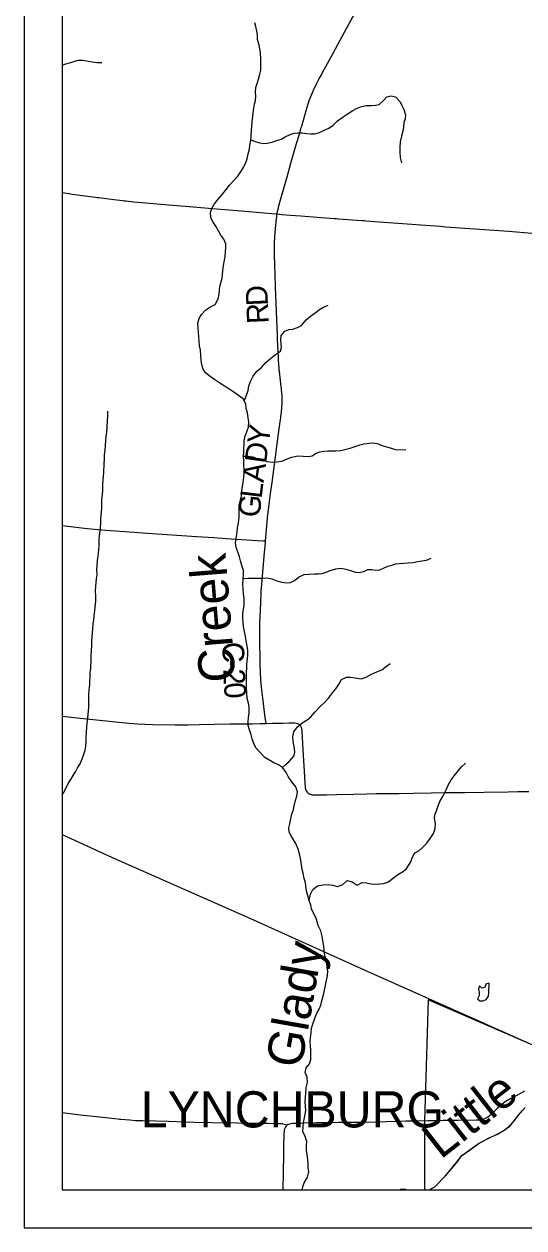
# Model space of a CAD drawing. Extents: x 0 to 48.6, y 0 to 22.
# Drawn here: x 2 to 3.311, y 14 to 17.154 of the extents above; entities that cross this region are included whole.
import ezdxf

# ---------------------------------------------------------------- set-up
doc = ezdxf.new("R2010")
doc.units = 0
for name, color, linetype in [('GM_X_Corporation', 7, 'Continuous'), ('GM_X_Corporation_Text', 7, 'Continuous'), ('GM_X_County_Road', 7, 'Continuous'), ('GM_X_County_Road_Text', 7, 'Continuous'), ('GM_X_Major_River', 7, 'Continuous'), ('GM_X_Major_River_Text', 7, 'Continuous'), ('GM_X_Minor_Lake', 7, 'Continuous'), ('GM_X_Minor_River', 7, 'Continuous'), ('GM_X_Minor_River_Text', 7, 'Continuous'), ('GM_X_Rail_Line', 7, 'Continuous'), ('GM_X_Township_Road', 7, 'Continuous'), ('SH_Data', 7, 'Continuous')]:
    doc.layers.add(name, color=color, linetype=linetype)

msp = doc.modelspace()

# ---------------------------------------------------------------- linework, layer by layer
at = {"layer": 'GM_X_Corporation'}
for points in [[(2.1, 20.9), (2.1, 14.1), (2.9857, 14.1), (2.9884, 14.1013), (3.0002, 14.1003), (3.0023, 14.1), (3.0623, 14.1), (3.0767, 14.1079), (3.1042, 14.1359), (3.1217, 14.1568), (3.1377, 14.1755), (3.1474, 14.1893), (3.1702, 14.2056), (3.191, 14.2204), (3.2179, 14.2355), (3.2416, 14.246), (3.2589, 14.2563), (3.2735, 14.2663), (3.2887, 14.2846), (3.2996, 14.2996), (3.3136, 14.3153)], [(2.1, 20.9), (2.1, 14.1), (2.9857, 14.1), (2.9884, 14.1013), (3.0002, 14.1003), (3.0023, 14.1), (3.0623, 14.1), (3.0767, 14.1079), (3.1042, 14.1359), (3.1217, 14.1568), (3.1377, 14.1755), (3.1474, 14.1893), (3.1702, 14.2056), (3.191, 14.2204), (3.2179, 14.2355), (3.2416, 14.246), (3.2589, 14.2563), (3.2735, 14.2663), (3.2887, 14.2846), (3.2996, 14.2996), (3.3136, 14.3153)], [(3.3339, 14.4793), (3.0597, 14.5973), (3.0499, 14.2798), (3.0498, 14.1), (3.0622, 14.1), (3.0767, 14.1079), (3.1048, 14.1365), (3.1347, 14.1718), (3.1478, 14.1896), (3.1817, 14.2139), (3.1919, 14.2209), (3.2084, 14.2298), (3.2183, 14.2356), (3.2408, 14.2454), (3.259, 14.2564), (3.275, 14.268), (3.2871, 14.2826), (3.2959, 14.2944), (3.3067, 14.3077), (3.3137, 14.3153)]]:
    msp.add_lwpolyline(points, dxfattribs=at)
msp.add_lwpolyline([(2.9857, 14.1), (3.0023, 14.1), (3.0002, 14.1003), (2.9884, 14.1013)], close=True, dxfattribs=at)
msp.add_lwpolyline([(2.9857, 14.1), (3.0023, 14.1), (3.0002, 14.1003), (2.9884, 14.1013)], close=True, dxfattribs=at)
at = {"layer": 'GM_X_County_Road'}
for points in [[(2.6637, 16.6568), (2.664, 16.6587), (2.6649, 16.6632), (2.6662, 16.6697), (2.6671, 16.6737), (2.6682, 16.6782), (2.6695, 16.683), (2.6709, 16.6878), (2.6898, 16.7541), (2.6998, 16.7901), (2.7147, 16.8414), (2.721, 16.8629), (2.7261, 16.8802), (2.7269, 16.8831), (2.728, 16.8867), (2.7416, 16.9339), (2.746, 16.9481), (2.7478, 16.9537), (2.75, 16.9599), (2.7518, 16.9646), (2.7543, 16.971), (2.757, 16.9771), (2.7601, 16.9841), (2.7632, 16.9903), (2.7667, 16.9975), (2.7697, 17.0032), (2.7733, 17.0099), (2.7786, 17.02), (2.7818, 17.0258), (2.7868, 17.035), (2.8093, 17.0762), (2.8224, 17.1009), (2.8518, 17.1542), (2.8663, 17.181)], [(2.1, 16.7127), (2.1189, 16.71), (2.1224, 16.7095), (2.1263, 16.709), (2.1873, 16.7008), (2.1914, 16.7003), (2.196, 16.6997), (2.2357, 16.6944), (2.2508, 16.6927), (2.2581, 16.6918), (2.2629, 16.6912), (2.2665, 16.6909), (2.2882, 16.6886), (2.3695, 16.6814), (2.412, 16.6778), (2.443, 16.6752), (2.4839, 16.6718), (2.5693, 16.6651), (2.6498, 16.6582), (2.6637, 16.6568)], [(2.6332, 15.8001), (2.6347, 15.8192), (2.6387, 15.8607), (2.642, 15.8897), (2.6464, 15.9242), (2.6502, 15.9532), (2.6594, 16.0203), (2.6631, 16.0474), (2.6692, 16.0936), (2.6726, 16.1179), (2.6732, 16.1219), (2.6736, 16.1257), (2.6749, 16.1376), (2.6754, 16.1416), (2.6757, 16.1456), (2.676, 16.1491), (2.6763, 16.1527), (2.6766, 16.1585), (2.6768, 16.1638), (2.6768, 16.1693), (2.6768, 16.1743), (2.6766, 16.1785), (2.6764, 16.1823), (2.6762, 16.1855), (2.6758, 16.1895), (2.6754, 16.1944), (2.6749, 16.2003), (2.6745, 16.204), (2.6726, 16.2207), (2.6697, 16.2445), (2.6693, 16.2478), (2.669, 16.2519), (2.6685, 16.2566), (2.6682, 16.2608), (2.6679, 16.2653), (2.6675, 16.2723), (2.6671, 16.2777), (2.6669, 16.2819), (2.6648, 16.3281), (2.6646, 16.3322), (2.6643, 16.3383), (2.6617, 16.4018), (2.6596, 16.4651), (2.6586, 16.4986), (2.657, 16.549), (2.6566, 16.5744), (2.6566, 16.5778), (2.6566, 16.5813), (2.6568, 16.5863), (2.6572, 16.5906), (2.6576, 16.5957), (2.6586, 16.6086), (2.6622, 16.6455), (2.6625, 16.6488), (2.6631, 16.6527), (2.6637, 16.6568)], [(2.6637, 16.6568), (2.6758, 16.6555), (2.6981, 16.6538), (2.726, 16.6518), (2.7786, 16.6477), (2.8142, 16.6451), (2.8189, 16.6448), (2.8244, 16.6444), (2.886, 16.6398), (2.8914, 16.6394), (2.8967, 16.639), (2.9311, 16.6365), (2.9924, 16.6318), (3.0649, 16.6267), (3.0931, 16.6244), (3.0984, 16.624), (3.1052, 16.6235), (3.2713, 16.6113), (3.3512, 16.605)], [(2.6348, 15.3218), (2.6323, 15.3382), (2.6302, 15.3518), (2.6275, 15.374), (2.6228, 15.4169), (2.6224, 15.4203), (2.6221, 15.4238), (2.6207, 15.4402), (2.6204, 15.4441), (2.6202, 15.4477), (2.62, 15.4513), (2.6198, 15.4557), (2.6197, 15.46), (2.6196, 15.4639), (2.6195, 15.4675), (2.6194, 15.4711), (2.6194, 15.4753), (2.6192, 15.4992), (2.6186, 15.5265), (2.618, 15.5489), (2.6179, 15.5651), (2.6184, 15.5874), (2.6196, 15.6179), (2.6217, 15.6623), (2.6219, 15.6663), (2.6221, 15.6697), (2.6233, 15.6855), (2.6298, 15.7598), (2.6329, 15.7963), (2.6332, 15.8001)], [(2.1, 15.3409), (2.1395, 15.3368), (2.2488, 15.3249), (2.2754, 15.3224), (2.2977, 15.3207), (2.317, 15.3196), (2.3369, 15.3187), (2.3959, 15.3183), (2.4301, 15.3186), (2.4593, 15.319), (2.5394, 15.3205), (2.599, 15.3211), (2.6189, 15.3215), (2.6348, 15.3218)], [(2.6348, 15.3218), (2.6506, 15.3222), (2.6711, 15.3228), (2.6786, 15.3229), (2.6947, 15.3234), (2.7058, 15.3235), (2.7101, 15.3232), (2.7137, 15.3226), (2.7166, 15.3218), (2.7192, 15.3205), (2.7217, 15.3188), (2.7233, 15.3172), (2.7247, 15.3153), (2.7257, 15.3135), (2.7266, 15.3116), (2.7271, 15.3099), (2.7274, 15.3083), (2.7278, 15.3064), (2.7281, 15.3042), (2.7283, 15.3015), (2.7307, 15.2524), (2.7356, 15.1818), (2.7366, 15.165), (2.7371, 15.1556), (2.7373, 15.1533), (2.7378, 15.1506), (2.7382, 15.149), (2.739, 15.1469), (2.7405, 15.1441), (2.7421, 15.142), (2.744, 15.1402), (2.7466, 15.1382), (2.7494, 15.1367), (2.7525, 15.1357), (2.7556, 15.135), (2.76, 15.1345), (2.7682, 15.1344), (2.7937, 15.1351), (2.8197, 15.1359), (2.8638, 15.1367), (2.8992, 15.1375), (2.9228, 15.1379), (2.9837, 15.1386), (3.0204, 15.1395), (3.0676, 15.1399), (3.1055, 15.1407), (3.1558, 15.1413), (3.2068, 15.1422), (3.2695, 15.143), (3.2944, 15.1433), (3.3236, 15.1437)], [(3.3126, 14.3586), (3.2903, 14.3464), (3.2804, 14.3411), (3.2761, 14.3388), (3.2724, 14.3368), (3.2684, 14.3344), (3.2641, 14.3317), (3.2605, 14.3294), (3.2572, 14.327), (3.2539, 14.3246), (3.2505, 14.3218), (3.2477, 14.3194), (3.2417, 14.314), (3.227, 14.2996), (3.2245, 14.2973), (3.222, 14.2951), (3.2192, 14.2928), (3.2162, 14.2905), (3.2129, 14.2885), (3.2088, 14.2864), (3.2055, 14.2851), (3.2024, 14.2841), (3.1982, 14.2832), (3.1934, 14.2825), (3.1893, 14.2823), (3.1854, 14.282), (3.168, 14.2819), (3.1488, 14.282), (3.1382, 14.2818), (3.1152, 14.2814), (3.099, 14.2812), (3.086, 14.2809), (3.0599, 14.2803)], [(2.1, 14.302), (2.1136, 14.3004), (2.155, 14.2957), (2.1722, 14.2936), (2.2143, 14.2892), (2.2462, 14.2857), (2.2501, 14.2853), (2.2538, 14.2849), (2.2773, 14.2828), (2.2921, 14.2818), (2.3113, 14.2811), (2.3784, 14.2793), (2.4213, 14.2781), (2.4467, 14.2774), (2.4927, 14.2764), (2.5604, 14.2754), (2.5983, 14.2746), (2.6274, 14.2746), (2.6386, 14.2744), (2.6634, 14.274), (2.6682, 14.2738), (2.6728, 14.2737), (2.6746, 14.2736), (2.6766, 14.2734), (2.6788, 14.2731), (2.6819, 14.2722), (2.6903, 14.2697)], [(2.6903, 14.2697), (2.6894, 14.2691), (2.6878, 14.2675), (2.6863, 14.2656), (2.6849, 14.2633), (2.6842, 14.262), (2.6836, 14.2604), (2.683, 14.2586), (2.6824, 14.2567), (2.682, 14.2545), (2.6816, 14.2523), (2.6812, 14.2479), (2.6801, 14.21), (2.6799, 14.1808), (2.6796, 14.1572), (2.6795, 14.1342), (2.6789, 14.1131), (2.6788, 14.1102), (2.6786, 14.1075), (2.6785, 14.1045), (2.6781, 14.1015), (2.678, 14.1)], [(3.0599, 14.2803), (3.025, 14.28), (3.0014, 14.2795), (2.9492, 14.2779), (2.9231, 14.2773), (2.8902, 14.2765), (2.8605, 14.276), (2.8257, 14.2758), (2.8003, 14.2757), (2.7668, 14.2752), (2.7345, 14.2746), (2.7146, 14.2739), (2.7047, 14.2732), (2.6996, 14.2727), (2.6962, 14.2721), (2.6937, 14.2714), (2.6916, 14.2705), (2.6903, 14.2697)]]:
    msp.add_lwpolyline(points, dxfattribs=at)
at = {"layer": 'GM_X_Major_River'}
msp.add_lwpolyline([(2.9873, 14.1), (2.9893, 14.1009), (3, 14.1)], dxfattribs=at)
msp.add_lwpolyline([(2.9873, 14.1), (2.9893, 14.1009), (3, 14.1)], dxfattribs=at)
at = {"layer": 'GM_X_Minor_Lake'}
for points in [[(3.2141, 14.6021), (3.2178, 14.6072), (3.2186, 14.6159), (3.2187, 14.625), (3.2199, 14.6341), (3.2196, 14.6417), (3.2116, 14.6399), (3.2085, 14.6308), (3.2063, 14.6301)], [(3.2063, 14.6301), (3.2001, 14.6282), (3.1945, 14.6344), (3.1918, 14.6256), (3.1932, 14.6173), (3.1931, 14.6089), (3.1892, 14.5999), (3.1953, 14.5952), (3.204, 14.5948), (3.212, 14.5985), (3.2141, 14.6021)]]:
    msp.add_lwpolyline(points, dxfattribs=at)
at = {"layer": 'GM_X_Minor_River'}
for points in [[(2.5619, 16.1813), (2.5499, 16.1902), (2.5367, 16.1987), (2.5254, 16.2053), (2.5111, 16.2154), (2.5006, 16.222), (2.4881, 16.2305), (2.4754, 16.2405), (2.4694, 16.2501), (2.4661, 16.2615), (2.464, 16.2737), (2.4635, 16.287), (2.4625, 16.2995), (2.46, 16.3117), (2.459, 16.325), (2.458, 16.3356), (2.4574, 16.3451), (2.4561, 16.3596), (2.4558, 16.3706), (2.4587, 16.3827), (2.4653, 16.3933), (2.4764, 16.406), (2.4875, 16.4123), (2.5009, 16.4198), (2.5091, 16.4345), (2.5112, 16.447), (2.5125, 16.4572), (2.5137, 16.4667), (2.5161, 16.4765), (2.5193, 16.4882), (2.5206, 16.4977), (2.5215, 16.5091), (2.5232, 16.5216), (2.5257, 16.536), (2.5273, 16.5466), (2.5283, 16.5583), (2.5288, 16.5686), (2.5289, 16.5785), (2.5238, 16.5907), (2.5159, 16.601), (2.5104, 16.611), (2.5029, 16.6251), (2.4947, 16.6366), (2.4896, 16.6477), (2.489, 16.661), (2.4925, 16.6708), (2.4996, 16.6836), (2.5092, 16.6956), (2.5204, 16.7088), (2.5301, 16.7212), (2.5386, 16.7321), (2.5517, 16.746), (2.5605, 16.7561), (2.5679, 16.7666), (2.5753, 16.7787), (2.5815, 16.7915), (2.5847, 16.8017), (2.5879, 16.8142), (2.5911, 16.8263), (2.5924, 16.8362), (2.5948, 16.849), (2.5954, 16.8619), (2.596, 16.8764), (2.5969, 16.8858), (2.5978, 16.8987), (2.5995, 16.912), (2.6008, 16.9215), (2.6021, 16.934), (2.6045, 16.9446), (2.6065, 16.9544), (2.6078, 16.9658), (2.6072, 16.9753), (2.6081, 16.9882), (2.6113, 16.9988), (2.6149, 17.0101), (2.6185, 17.023), (2.6205, 17.0332), (2.621, 17.0457), (2.6205, 17.0613), (2.62, 17.0803), (2.6186, 17.0898), (2.6164, 17.0993), (2.6125, 17.1138), (2.6119, 17.1259), (2.6105, 17.1362), (2.6076, 17.1476), (2.6054, 17.1572)], [(2.1, 17.0471), (2.1003, 17.0471), (2.1098, 17.0501), (2.1228, 17.0541), (2.1331, 17.0573), (2.143, 17.0595), (2.1536, 17.0597), (2.165, 17.0577), (2.1783, 17.0556), (2.1908, 17.0539), (2.2041, 17.0541)], [(2.5949, 16.8514), (2.6085, 16.8462), (2.6183, 16.8434), (2.6282, 16.8418), (2.6377, 16.842), (2.6502, 16.8449), (2.6605, 16.8482), (2.6743, 16.8529), (2.685, 16.8593), (2.6976, 16.8652), (2.7079, 16.8681), (2.7182, 16.8698), (2.7292, 16.8693), (2.7413, 16.8676), (2.752, 16.8664), (2.7626, 16.8666), (2.7744, 16.8703), (2.787, 16.8765), (2.7989, 16.8817), (2.8104, 16.8899), (2.8216, 16.9008), (2.8365, 16.9116), (2.8469, 16.9187), (2.8618, 16.9276), (2.8714, 16.9328), (2.8851, 16.9387), (2.8965, 16.9412), (2.9114, 16.9414), (2.9216, 16.9416), (2.9311, 16.9438), (2.9419, 16.9531), (2.9512, 16.9636), (2.9618, 16.9661), (2.974, 16.9633), (2.9859, 16.9503), (2.9907, 16.9407), (2.9955, 16.9308), (3.0003, 16.9167), (2.9994, 16.9064), (2.9962, 16.8966), (2.9945, 16.8837), (2.9929, 16.8735), (2.9893, 16.8603), (2.9864, 16.8455), (2.9851, 16.8307), (2.9849, 16.8186), (2.9866, 16.8045), (2.9899, 16.7904)], [(2.5772, 16.1672), (2.5824, 16.1792), (2.5872, 16.1939), (2.5896, 16.2068), (2.5936, 16.2181), (2.6006, 16.2317), (2.6106, 16.2445), (2.6226, 16.2549), (2.6341, 16.2673), (2.6464, 16.2782), (2.6595, 16.289), (2.6725, 16.2972), (2.6749, 16.307), (2.6739, 16.3169), (2.6737, 16.3279), (2.6742, 16.3382), (2.6839, 16.3498), (2.6945, 16.3539), (2.7044, 16.3552), (2.7174, 16.3589), (2.7277, 16.3648), (2.7401, 16.3795), (2.7512, 16.3888), (2.7635, 16.3974), (2.775, 16.4067), (2.7854, 16.413), (2.7976, 16.4182)], [(2.7256, 14.9632), (2.7231, 14.977), (2.7188, 14.9922), (2.7129, 15.0071), (2.7065, 15.0166), (2.7002, 15.027), (2.695, 15.0369), (2.694, 15.0479), (2.6965, 15.0585), (2.6989, 15.0688), (2.7025, 15.0839), (2.7061, 15.0964), (2.7078, 15.1062), (2.7106, 15.1172), (2.7153, 15.1312), (2.717, 15.1429), (2.713, 15.1555), (2.7021, 15.1689), (2.6928, 15.1831), (2.6873, 15.193), (2.6776, 15.2061), (2.6674, 15.213), (2.6553, 15.2189), (2.6316, 15.2325), (2.6188, 15.2456), (2.6084, 15.2567), (2.6028, 15.2682), (2.5984, 15.2811), (2.5959, 15.2922), (2.5911, 15.3048), (2.5879, 15.3166), (2.5876, 15.3268), (2.5886, 15.3374), (2.5898, 15.3488), (2.5901, 15.3651), (2.5883, 15.3746), (2.5854, 15.3868), (2.5841, 15.4024), (2.5835, 15.4138), (2.5832, 15.4233), (2.5834, 15.4354), (2.5832, 15.4461), (2.5833, 15.4559), (2.5838, 15.4673), (2.5844, 15.4772), (2.5857, 15.4912), (2.587, 15.5018), (2.5871, 15.5136), (2.5836, 15.5341), (2.5804, 15.5494), (2.5779, 15.5631), (2.5754, 15.576), (2.5744, 15.5855), (2.5734, 15.5977), (2.574, 15.6106), (2.5753, 15.6201), (2.5769, 15.6318), (2.5774, 15.6413), (2.5768, 15.6512), (2.5758, 15.6607), (2.5749, 15.6747), (2.5739, 15.6869), (2.5744, 15.6994), (2.575, 15.7127), (2.5755, 15.7222), (2.5711, 15.7359), (2.5679, 15.7477), (2.565, 15.758), (2.5613, 15.769), (2.5569, 15.7805), (2.5548, 15.7942), (2.5565, 15.8075), (2.559, 15.8234), (2.5599, 15.8347), (2.562, 15.8476), (2.5641, 15.8616), (2.5644, 15.8818), (2.5638, 15.8939), (2.5665, 15.9037), (2.5702, 15.9181), (2.5711, 15.931), (2.5724, 15.9432), (2.5744, 15.9534), (2.5761, 15.967), (2.5767, 15.9776), (2.5768, 15.9871), (2.5765, 15.9978), (2.576, 16.0107), (2.5753, 16.0206), (2.5763, 16.0354), (2.5767, 16.0615), (2.5791, 16.0729), (2.5838, 16.0861), (2.5882, 16.0982), (2.5895, 16.1122), (2.5877, 16.1225), (2.5856, 16.1358), (2.5827, 16.1473), (2.5818, 16.1594), (2.5743, 16.172), (2.5619, 16.1813)], [(2.1, 15.1344), (2.1031, 15.1398), (2.1109, 15.1545), (2.116, 15.1647), (2.1226, 15.1753), (2.1284, 15.1855), (2.1346, 15.1952), (2.1404, 15.2058), (2.1467, 15.2163), (2.1525, 15.2292), (2.1561, 15.239), (2.1601, 15.2515), (2.1617, 15.2621), (2.1627, 15.2769), (2.1632, 15.2867), (2.1641, 15.2989), (2.165, 15.3118), (2.1656, 15.3228), (2.1669, 15.3357), (2.1696, 15.3645), (2.1701, 15.3759), (2.1702, 15.3857), (2.17, 15.3975), (2.1709, 15.41), (2.1723, 15.4241), (2.1728, 15.4335), (2.1733, 15.4438), (2.1734, 15.4544), (2.1751, 15.4658), (2.1762, 15.4908), (2.1763, 15.5003), (2.1769, 15.5132), (2.1774, 15.5272), (2.178, 15.5371), (2.1785, 15.5493), (2.1794, 15.5591), (2.1807, 15.5693), (2.1816, 15.5826), (2.1829, 15.5928), (2.1842, 15.605), (2.1855, 15.6164), (2.1864, 15.6266), (2.1881, 15.6425), (2.1883, 15.6554), (2.1877, 15.6695), (2.1886, 15.6808), (2.1895, 15.6911), (2.19, 15.7006), (2.1913, 15.7112), (2.1911, 15.7249), (2.1916, 15.7351), (2.1926, 15.7484), (2.1939, 15.7601), (2.1965, 15.7867), (2.197, 15.7965), (2.1972, 15.8068), (2.1989, 15.8197), (2.2006, 15.8341), (2.2011, 15.8462), (2.2016, 15.8568), (2.2018, 15.8667), (2.203, 15.8766), (2.2036, 15.8872), (2.2038, 15.9069), (2.2056, 15.9221), (2.2065, 15.9335), (2.2067, 15.949), (2.2072, 15.9604), (2.2081, 15.9699), (2.2094, 15.9797), (2.2097, 16.0025), (2.2106, 16.015), (2.2111, 16.0256), (2.2124, 16.0382), (2.2134, 16.0499), (2.2143, 16.0632), (2.2156, 16.0734), (2.2172, 16.0852), (2.2182, 16.0981), (2.2192, 16.1148), (2.2197, 16.1277), (2.2199, 16.1398)], [(2.5754, 16.0223), (2.5871, 16.0219), (2.5996, 16.0202), (2.6151, 16.0144), (2.6254, 16.0119), (2.6375, 16.0084), (2.6504, 16.0067), (2.6629, 16.0069), (2.6762, 16.009), (2.69, 16.0153), (2.7022, 16.0193), (2.7182, 16.0229), (2.7322, 16.0223), (2.7455, 16.0214), (2.755, 16.0232), (2.7646, 16.0291), (2.7757, 16.0332), (2.7856, 16.0353), (2.7962, 16.0363), (2.8171, 16.036), (2.8308, 16.037), (2.8407, 16.0395), (2.8552, 16.0435), (2.8686, 16.0475), (2.8808, 16.0519), (2.8911, 16.0548), (2.9048, 16.0562), (2.9173, 16.0571), (2.9287, 16.0547), (2.9411, 16.0496), (2.957, 16.0449), (2.9676, 16.0413), (2.9775, 16.0385), (3.001, 16.0397)], [(2.5745, 15.7014), (2.5885, 15.7023), (2.6014, 15.7029), (2.6125, 15.7027), (2.6258, 15.7029), (2.6364, 15.7032), (2.65, 15.7007), (2.6625, 15.6956), (2.6761, 15.6924), (2.6875, 15.6904), (2.6989, 15.691), (2.7089, 15.6962), (2.7196, 15.7051), (2.7345, 15.7125), (2.7475, 15.7131), (2.7615, 15.7141), (2.7722, 15.7139), (2.782, 15.7146), (2.7923, 15.7186), (2.8027, 15.7223), (2.8171, 15.7266), (2.8316, 15.7287), (2.8441, 15.7263), (2.8558, 15.7223), (2.8691, 15.718), (2.8786, 15.7171), (2.8911, 15.72), (2.9018, 15.7248), (2.9117, 15.7254), (2.9219, 15.7238), (2.933, 15.7244), (2.9441, 15.7292), (2.954, 15.734), (2.9639, 15.7369), (2.9746, 15.7402), (2.9841, 15.7412), (2.9959, 15.7418), (3.0073, 15.7424), (3.0198, 15.7434), (3.0313, 15.7459), (3.0434, 15.7476), (3.0556, 15.7501), (3.0678, 15.7545)], [(2.6776, 15.206), (2.6834, 15.2125), (2.6953, 15.2222), (2.7072, 15.2357), (2.71, 15.2455), (2.709, 15.2558), (2.7072, 15.2653), (2.7059, 15.2763), (2.7045, 15.2866), (2.7073, 15.2995), (2.7174, 15.3126), (2.7293, 15.3235), (2.7423, 15.3317), (2.7519, 15.3395), (2.7631, 15.3519), (2.7751, 15.365), (2.7885, 15.3774), (2.7985, 15.3883), (2.809, 15.4018), (2.8171, 15.4127), (2.8264, 15.4255), (2.8322, 15.4372), (2.8452, 15.4427), (2.8555, 15.4433), (2.8684, 15.4416), (2.8843, 15.4388), (2.8973, 15.4432), (2.9111, 15.4513), (2.9248, 15.4568), (2.9382, 15.4624), (2.9501, 15.4721), (2.9601, 15.4788)], [(3.0142, 14.959), (3.0178, 14.9701), (3.0248, 14.9829), (3.0351, 14.9885), (3.0455, 14.9975), (3.0559, 15.0079), (3.0652, 15.0207), (3.0737, 15.0335), (3.0781, 15.0464), (3.0786, 15.0597), (3.0765, 15.0726), (3.0774, 15.0828), (3.0817, 15.0927), (3.0861, 15.1063), (3.0904, 15.1176), (3.099, 15.1323), (3.1064, 15.1478), (3.113, 15.1621), (3.1197, 15.1742), (3.1274, 15.1843), (3.1359, 15.1944), (3.1463, 15.2072), (3.1575, 15.2181)], [(2.7589, 14.8244), (2.754, 14.8358), (2.7515, 14.8453), (2.7474, 14.8575), (2.743, 14.8735), (2.7409, 14.8834), (2.7391, 14.8944), (2.738, 14.9047), (2.7347, 14.9157), (2.7322, 14.9298), (2.7293, 14.9393), (2.7271, 14.9511), (2.7256, 14.9632)], [(2.7474, 14.8575), (2.7514, 14.8742), (2.7572, 14.8866), (2.7698, 14.8964), (2.7835, 14.8993), (2.7972, 14.8995), (2.809, 14.8979), (2.8222, 14.8943), (2.8359, 14.8995), (2.8474, 14.91), (2.8607, 14.9065), (2.8735, 14.8984), (2.8861, 14.9055), (2.8978, 14.9046), (2.9092, 14.9014), (2.9198, 14.9006), (2.9327, 14.9016), (2.9422, 14.9026), (2.9559, 14.907), (2.9693, 14.9179), (2.9819, 14.9273), (2.9922, 14.9329), (3.0018, 14.9396), (3.0142, 14.959)], [(2.7292, 14.1), (2.731, 14.108), (2.7345, 14.1182), (2.7434, 14.1329), (2.747, 14.1469), (2.7452, 14.1575), (2.7449, 14.1678), (2.7443, 14.1784), (2.7421, 14.1921), (2.7407, 14.2035), (2.7409, 14.2164), (2.7413, 14.2267), (2.7369, 14.2396), (2.731, 14.253), (2.7315, 14.2659), (2.7324, 14.2765), (2.7351, 14.2882), (2.7371, 14.2981), (2.7384, 14.3079), (2.7381, 14.3182), (2.7367, 14.3307), (2.7376, 14.3429), (2.7385, 14.3531), (2.7394, 14.3675), (2.7429, 14.3811), (2.7427, 14.3948), (2.7375, 14.4074), (2.7395, 14.4199), (2.748, 14.4297), (2.7523, 14.4414), (2.7517, 14.4547), (2.7518, 14.4665), (2.7511, 14.476), (2.7501, 14.4881), (2.751, 14.498), (2.7526, 14.5113), (2.7535, 14.5234), (2.7578, 14.5366), (2.7625, 14.5499), (2.7679, 14.5627), (2.7741, 14.5729), (2.7784, 14.5839), (2.7816, 14.5987), (2.7848, 14.6108), (2.7891, 14.6308), (2.7923, 14.6452), (2.7959, 14.6608), (2.7964, 14.6744), (2.795, 14.6839), (2.794, 14.6934), (2.7914, 14.7041), (2.7878, 14.7182), (2.7867, 14.7284), (2.7864, 14.7383), (2.7832, 14.752), (2.7818, 14.7642), (2.7785, 14.7782), (2.7714, 14.792), (2.7681, 14.8023), (2.7656, 14.8118), (2.7589, 14.8244)]]:
    msp.add_lwpolyline(points, dxfattribs=at)
at = {"layer": 'GM_X_Rail_Line'}
msp.add_lwpolyline([(2.1, 15.0305), (2.2297, 14.9717), (2.5941, 14.811), (2.8918, 14.676), (3.3664, 14.4649)], dxfattribs=at)
at = {"layer": 'GM_X_Township_Road'}
msp.add_lwpolyline([(2.1, 15.8401), (2.1652, 15.8328), (2.1943, 15.8298), (2.2037, 15.8291), (2.2141, 15.8282), (2.2519, 15.8255), (2.3238, 15.8208), (2.4521, 15.8118), (2.498, 15.8088), (2.5302, 15.8066), (2.5699, 15.8042), (2.6114, 15.8013), (2.6275, 15.8004), (2.6332, 15.8001)], dxfattribs=at)
at = {"layer": 'SH_Data'}
for p, q in [((2, 21), (2, 14)), ((2.1, 20.9), (2.1, 14.1)), ((2.1, 14.1), (8.9, 14.1)), ((2.1, 14.1), (2.1, 14.1)), ((2, 14), (9, 14))]:
    msp.add_line(p, q, dxfattribs=at)

# ---------------------------------------------------------------- texts
at = {"layer": 'GM_X_Corporation_Text'}
msp.add_text('LYNCHBURG', height=0.0947, rotation=0, dxfattribs=at).set_placement((2.306, 14.2633))
at = {"layer": 'GM_X_County_Road_Text'}
for s, rotation, p in [('D', 92.4013, (2.6397, 16.4167)), ('R', 92.5377, (2.6417, 16.3701)), ('Y', 82.2116, (2.6412, 16.0505)), ('D', 82.2099, (2.6344, 16.001)), ('A', 82.3201, (2.6278, 15.9514)), ('L', 83.1397, (2.6227, 15.9095)), ('G', 84.1248, (2.6176, 15.86)), ('C', 272.0105, (2.5195, 15.5346)), ('2', 272.4523, (2.522, 15.4641)), ('-', 272.088, (2.5212, 15.4879)), ('0', 274.0888, (2.5236, 15.4274))]:
    msp.add_text(s, height=0.0568, rotation=rotation, dxfattribs=at).set_placement(p)
at = {"layer": 'GM_X_Major_River_Text'}
msp.add_text('Little', height=0.0947, rotation=38.1806, dxfattribs=at).set_placement((3.0921, 14.1778))
at = {"layer": 'GM_X_Minor_River_Text'}
for s, rotation, p in [('Creek', 94.5882, (2.5551, 15.4331)), ('Glady', 79.9972, (2.7265, 14.4156))]:
    msp.add_text(s, height=0.0947, rotation=rotation, dxfattribs=at).set_placement(p)

doc.saveas('drawing.dxf')
